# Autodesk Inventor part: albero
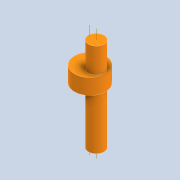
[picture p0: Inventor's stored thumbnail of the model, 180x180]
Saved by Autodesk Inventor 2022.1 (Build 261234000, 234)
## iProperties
Created: 2022-04
Part Number: albero
Material: Generico
Document SubType Name: Modeling
Designer: i911900
Density: 1 g/cm^3
Appearance: Arancione
Mass: 1.64772 g
Surface Area: 12.648 cm^2
Volume: 1.64772 cm^3
Author: i911900
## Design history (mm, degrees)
sketch "Schizzo1"
  geometry: C1 r 2.5 at (0, 0); 1 further point
  constraints: 1 centre point, 1 coincident
  dimensions: "d0" = 5 diameter of C1
extrude "Estrusione1" new body sketch "Schizzo1" distance "d1" = 30; taper "d2" = 0 deg
node "Piano di lavoro1"
sketch "Schizzo2"
  geometry: L1 (0, 0)-(-2, 0); C1 r 5 at (-2, 0)
  constraints: 2 end point, 1 centre point, 1 coincident, 1 horizontal
  dimensions: "d4" = 2 distance of L1.start L1.end; "d5" = 10 diameter of C1
extrude "Estrusione2" join sketch "Schizzo2" distance "d6" = 5; taper "d7" = 0 deg
sketch "Schizzo3"
  geometry: L1 (2, 0)-(18.164, 0); L2 (2, 2.5)-(11.924, 11.248); L3 (2, -2.5)-(11.924, -11.248); A1 r 15 centre (2, 0) between (10.578, -12.305) and (11.924, 11.248); A2 r 2.5 centre (2, 0) between (1.39, -2.424) and (2, 2.5) reference; 3 further points
  constraints: 6 end point, 4 point on circle, 2 symmetric about line, 1 centre point, 1 coincident, 1 horizontal
  dimensions: "d8" = 30 diameter of A1; "d12" = 8.57796 horizontal distance of A1.start point (2, 0)
extrude "Estrusione3" join sketch "Schizzo3" distance "d10" = 4; taper "d11" = 0 deg
node "Asse di lavoro1"
node "Asse di lavoro2"
node "Solido1"
other parameters: "d3" = -8
